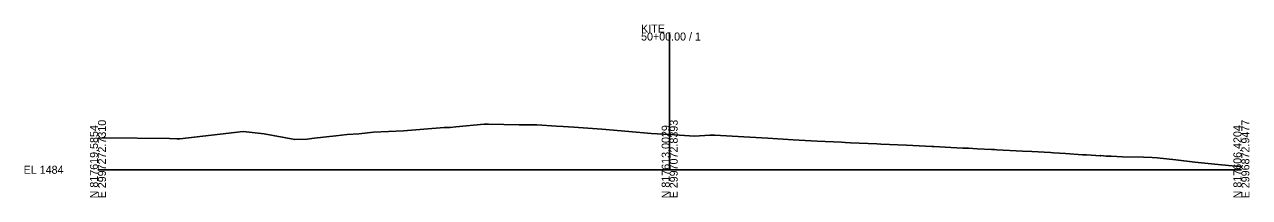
# Model space of a CAD drawing. Extents: x -26 to 2997147, y -10 to 817564.
# Drawn here: x -25.7 to 402.8, y -9.7 to 50.8 of the extents above; entities that cross this region are included whole.
import ezdxf

# ---------------------------------------------------------------- set-up
doc = ezdxf.new("R2010")
doc.units = 0
doc.layers.add('DESIGN - SHEET - Light Grid', color=7, linetype='Continuous')
doc.layers.add('SURVEY - GROUND - Top of Ground', color=7, linetype='Continuous')

msp = doc.modelspace()

# ---------------------------------------------------------------- linework, layer by layer
at = {"layer": 'DESIGN - SHEET - Light Grid'}
for p, q in [((200, 0), (200, 47.99)), ((0, 0), (200, 0)), ((200, 0), (400, 0))]:
    msp.add_line(p, q, dxfattribs=at)
at = {"layer": 'SURVEY - GROUND - Top of Ground'}
msp.add_lwpolyline([(0, 11.1), (1.59, 11.12), (2.51, 11.2), (24.99, 10.89), (27.64, 10.84), (28.59, 10.8), (50.85, 13.33), (58.09, 12.52), (68.84, 10.55), (73.2, 10.65), (75.61, 11), (83.17, 11.88), (87.22, 12.38), (91.23, 12.55), (96.34, 13.2), (106.92, 13.63), (121.07, 14.75), (123.19, 14.77), (125.2, 15.04), (135.15, 16), (136.65, 15.98), (147.4, 15.76), (153.56, 15.7), (160.42, 15.27), (162.78, 15.17), (166.53, 14.95), (176.28, 14.17), (185.74, 13.39), (193.51, 12.66), (200, 12.29), (208.69, 11.8), (214.04, 12.11), (215.52, 12.08), (215.83, 12.06), (225.93, 11.49), (232.24, 11.13), (234.34, 11.02), (243.19, 10.51), (251.57, 10.04), (260.11, 9.65), (261.36, 9.57), (263.29, 9.46), (272.47, 9.05), (273.89, 8.99), (282.8, 8.59), (291.67, 8.19), (292.37, 8.15), (298.4, 7.83), (302.53, 7.61), (304.56, 7.51), (307.56, 7.35), (312.64, 7.1), (313.58, 7.05), (314.49, 7), (323.4, 6.53), (326.72, 6.34), (333.17, 5.99), (334.23, 5.92), (338.51, 5.69), (344.47, 5.25), (345.85, 5.18), (350.73, 4.86), (350.79, 5.03), (352.75, 4.81), (354.42, 4.7), (358.45, 4.52), (365.77, 4.39), (368.83, 4.34), (370.54, 4.13), (377.11, 3.43), (383.74, 2.67), (393.04, 1.73), (399.26, 1.18), (400, 0.99)], dxfattribs=at)

# ---------------------------------------------------------------- texts
at = {"layer": 'DESIGN - SHEET - Light Grid'}
for s, p in [('50+00.00 / 1', (190, 45.19)), ('KITE', (190, 47.99)), ('EL 1484', (-26, -1.4))]:
    msp.add_text(s, height=2.8, dxfattribs=at).set_placement(p)
for s, p in [('E 2997272.7310', (2.8, -10)), ('E 2997072.8393', (202.8, -10)), ('E 2996872.9477', (402.8, -10)), ('N 817619.5854', (0, -10)), ('N 817613.0029', (200, -10)), ('N 817606.4204', (400, -10))]:
    msp.add_text(s, height=2.8, rotation=90, dxfattribs=at).set_placement(p)

doc.saveas('drawing.dxf')
